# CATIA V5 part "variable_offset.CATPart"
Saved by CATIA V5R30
Part number: Part1
Bounding box of the stored display mesh (mm): x -40 to 40, y -142.035 to 125.092, z -43.841 to 47.521
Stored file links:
  D:\PROJECTS\CATIA V56R 2020\Resources\Parts File\c17_catia_v6_6r2020_prt\variable_offset.CATPart
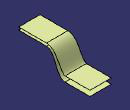
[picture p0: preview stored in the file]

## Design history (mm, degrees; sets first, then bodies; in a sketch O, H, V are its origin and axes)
Set1
  Sketch1 on yz-plane, origin (0, 0, 0), H (0, 1, 0), V (0, 0, 1)
    line L1 (-37.9526, 37.5213) -> (-142.0346, 37.5213)
    horizontal: L1 H
  Sketch2 on yz-plane, origin (0, 0, 0), H (0, 1, 0), V (0, 0, 1)
    line L1 (31.6324, -43.8406) -> (125.0922, -43.8406)
    horizontal: L1 H
  Extrude1: Element1 Sketch1, Lim1 40, Lim2 40
  Extrude2: Element1 Sketch2, Lim1 40, Lim2 40
  Blend1: StartLimit {blendlimit Curve edge of Extrude1, Support Extrude1}, EndLimit {blendlimit Curve edge of Extrude2, Support Extrude2}
  Join1: Elements (Extrude1; Blend1; Extrude2)
  GSOVariableOffset1: GlobalSurface Join1, ListOfConstraints Blend1
Body1 (main body)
